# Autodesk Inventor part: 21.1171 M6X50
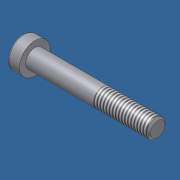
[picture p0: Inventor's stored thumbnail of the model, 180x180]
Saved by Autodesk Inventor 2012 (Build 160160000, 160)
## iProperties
Created: 2006-02
Part Number: 21.1171 M6X50
Material: Steel, Mild
Description: Cylinder Head Cap Screw
Document SubType Name: Modeling
Standard: DIN 7984
Designer: Andy Moles
Standards Organization: DIN
Language: en-US
Size Designation: M6 x 40
Categories: <MemberInstance><Categories><Category DisplayName="Fasteners" InternalName="e4da775c-781d-43d5-af7c-5136215cf5a6" Mnemonic="FSTN"><Category DisplayName="Bolts"
Density: 7.86 g/cm^3
Mass: 13.1529 g
Surface Area: 12.5505 cm^2
Volume: 1.6734 cm^3
Author: Andy Moles
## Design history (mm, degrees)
workplane "Work Plane1"
revolve "Body" stored, may be unused: angle "d10" = 90 deg
sketch "Sketch2"
  geometry: L1 (0, -6)-(0, 8) reference; L2 (-6, 0)-(8, 0) reference; L3 (2.309, 0)-(1.155, -2); L4 (1.155, -2)-(-1.155, -2); L5 (-1.155, -2)-(-2.309, 0); L6 (-2.309, 0)-(-1.155, 2); L7 (-1.155, 2)-(1.155, 2); L8 (1.155, 2)-(2.309, 0); 2 further points
  constraints: 12 end point, 1 coincident, 1 horizontal alignment, 1 point on line, 12 other
extrude "Slot" join sketch "Sketch2" stored distance "d11" = 10; taper "d12" = 0 deg
body "Solid1"
fillet "Fillet1" dims "d17" = 0.6 (= RR)
feature "Thread" dims "d13" = 18 (= GEL), "d14" = 0
chamfer "Chamfer1" distance "d15" = 0.61345 (= -0.5 x SPD + 0.5 x GD); stored, may be unused: second distance "d16" = 0.61345 (= GUL), angle "d27" = 45 deg
sketch "Sketch1"
  geometry: L1 (0.333, 0)-(50, 0); L2 (50, 0)-(50, 3); L3 (50, 3)-(32, 3); L4 (32, 3)-(31.386, 3); L5 (31.386, 3)-(0, 3); L6 (0, 3)-(0, 5); L7 (0, 5)-(-4, 5); L8 (-4, 5)-(-4, 2.309); L9 (-4, 2.309)-(-1, 2.309); L10 (-1, 2.309)-(0.333, 0); L11 (-8.4, 0)-(53.2, 0) reference; L12 (0, -0.5)-(0, 6.5) reference; L13 (32, 3)-(0, 3)
  constraints: 22 end point, 6 parallel, 2 collinear, 2 perpendicular, 1 horizontal, 1 midpoint
  dimensions: "d1" = 18 distance from line of L3.end L2 (= GEL); "d2" = 0.61355 distance of L4.end L3.end (computed from GAL); "d3" = 4 distance between parallel lines of L8 L6 (= KOH); "d4" = 3 distance of L8.end L9.end (= INTI); "d5" = 60 deg angle of L10 L1; "d6" = 6 diameter of L3 L1 (= GD); "d7" = 6 diameter of L5 L1 (= BDM); "d8" = 4.6188 diameter of L9 L1 (= 1.1547 x SW); "d9" = 10 diameter of L7 L1 (= KOD); "d26" = 50 distance between parallel lines of L12 L2 (= NLG)
other parameters: "GD" = 6 (= NND) [user parameter; used in 2 equation terms], "NLG" = 50 [user parameter; used in 1 equation term], "GEL" = 18 [user parameter; used in 2 equation terms], "KOD" = 10 [user parameter; used in 1 equation term], "KOH" = 4 [user parameter; used in 1 equation term], "INTI" = 3 [user parameter; used in 1 equation term], "GAL" = 0.61345 (= 0.61345 x PTC) [user parameter; used in 1 equation term], "GUL" = 0.61345 (= 0.61345 x PTC) [user parameter; used in 1 equation term], "BDM" = 6 (= NND) [user parameter; used in 1 equation term], "SW" = 4 [user parameter; used in 2 equation terms], "RR" = 0.6 [user parameter; used in 1 equation term], "SPD" = 4.7731 (= NND - 1.2269 x PTC) [user parameter; used in 1 equation term], "d19" = 0, "d28" = 0, "d29" = 0, "TOA" = 30 deg [user parameter], "GD1" = 4.7731 (= THREADDIA - 1.2269 x PTC) [user parameter], "THREADDIA" = 6 [user parameter; used in 1 equation term], "FAWI" = 45 deg [user parameter], "ANG" = 120 deg [user parameter], "PTC" = 1 [user parameter; used in 5 equation terms], "NND" = 6 [user parameter; used in 3 equation terms], "E0" = 4.62 (= 1.155 x SW) [user parameter]
